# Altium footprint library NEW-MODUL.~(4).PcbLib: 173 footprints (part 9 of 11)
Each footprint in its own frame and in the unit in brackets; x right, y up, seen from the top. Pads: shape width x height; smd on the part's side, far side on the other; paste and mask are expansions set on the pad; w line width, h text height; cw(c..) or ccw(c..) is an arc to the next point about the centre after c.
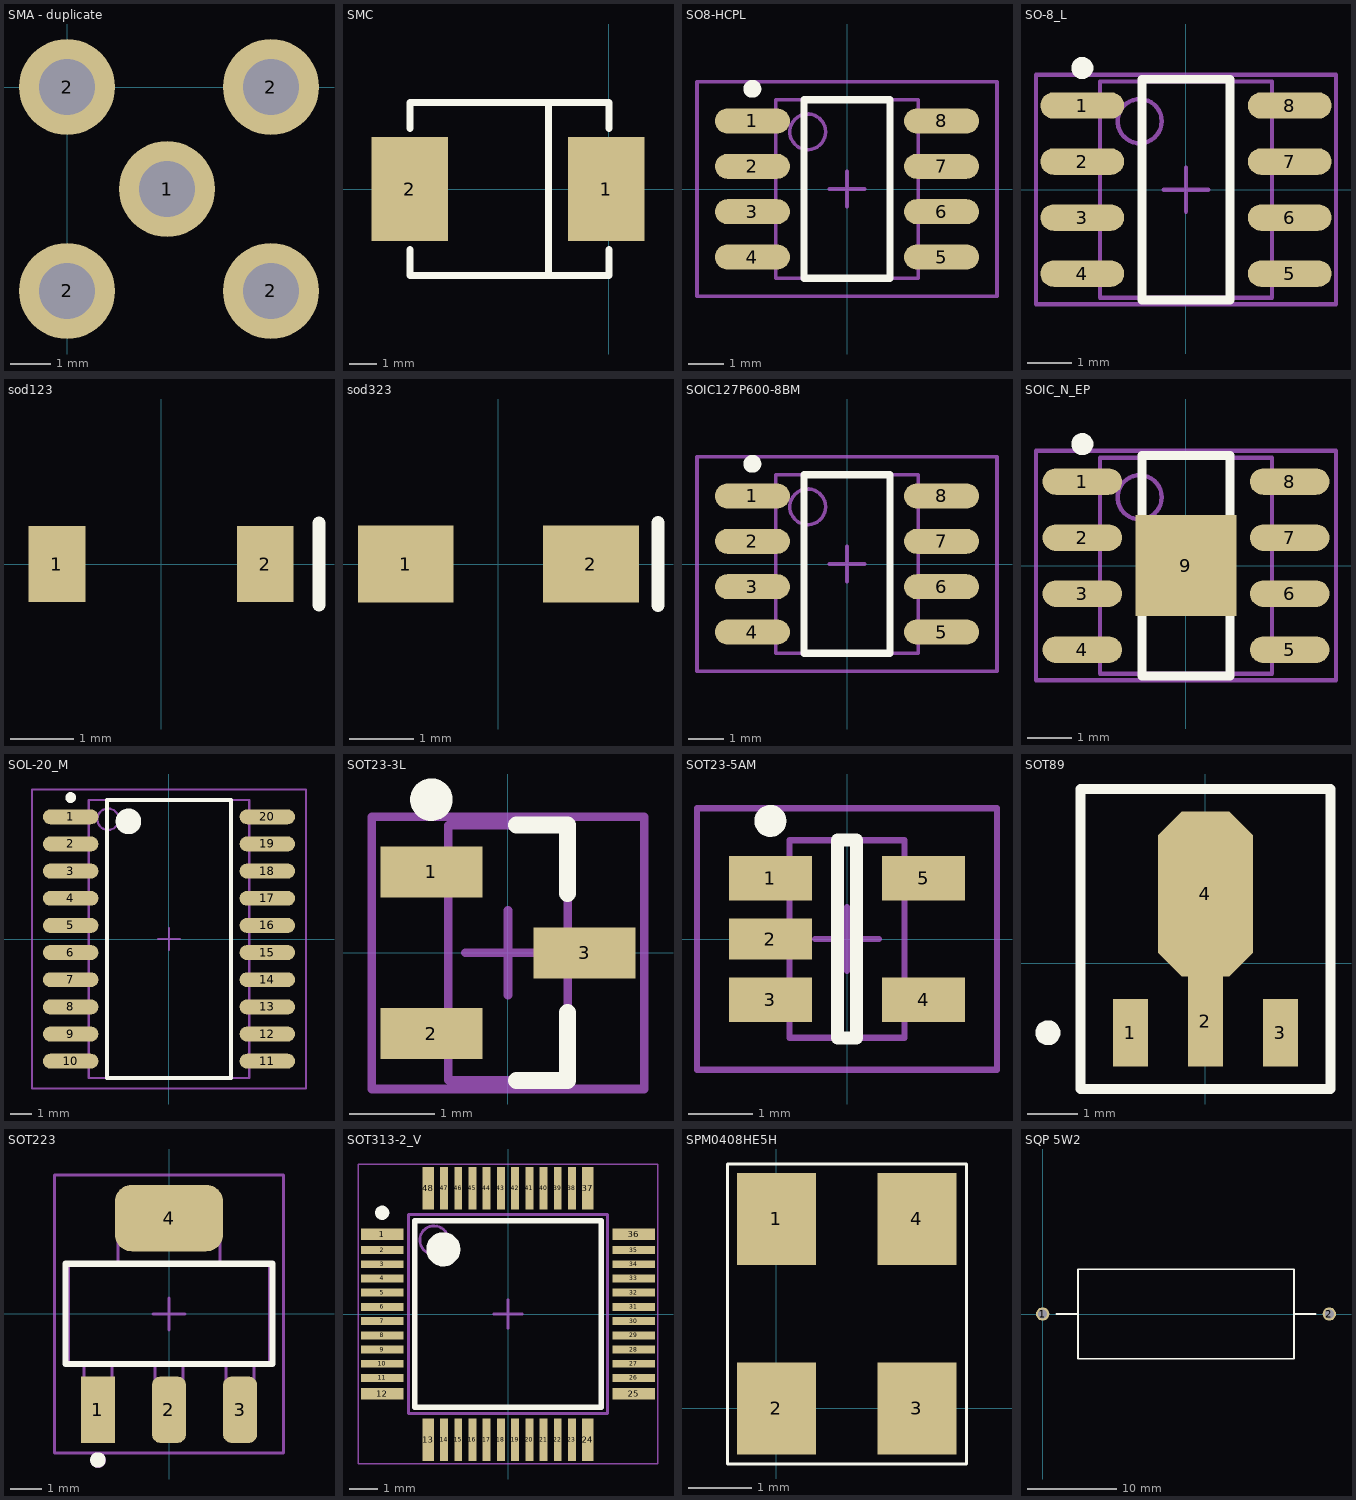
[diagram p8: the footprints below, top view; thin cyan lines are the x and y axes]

## SMA - duplicate [mm]
pads (5):
  round 2.4 hole 1.4: 1(2.5,-2.55) 2(0,-5.1) 2(0,0) 2(5.1,-5.1) 2(5.1,0)
3D body "11945.stp": height 10.43, standoff -3.41, extent -0.7,-13.7 5.64,0.5

## SMC [mm]
pads (2):
  rect 2.8x3.8 smd: 1(-0.102,0) 2(-7.302,0)
Top Overlay:
  lines w0.254: -7.302,-2.222 -7.302,-3.175 0,-3.175 0,-2.222 ; -7.302,2.222 -7.302,3.175 0,3.175 0,2.222 ; -2.222,-3.175 -2.222,3.175
3D body "User Library-Diode Molded Body.step": height 2.18, standoff 0.02, extent -7.633,-3 0.267,3

## SO8-HCPL [mm] "SOIC, 8-Leads, Body 4.9x3.9mm, Pitch 1.27mm, IPC Low Density"
height 2.59
pads (8):
  oval 2.1x0.7 smd: 1(-2.65,1.905) 2(-2.65,0.635) 3(-2.65,-0.635) 4(-2.65,-1.905) 5(2.65,-1.905) 6(2.65,-0.635) 7(2.65,0.635) 8(2.65,1.905)
Top Overlay:
  circle w0.25: c-2.65,2.805 r0.125
  lines w0.2: -1.2,-2.5 1.2,-2.5 1.2,2.5 -1.2,2.5 -1.2,-2.5
Mechanical 13:
  circle w0.1: c-1.1,1.6 r0.5
  lines w0.1: -2,-2.5 2,-2.5 2,2.5 -2,2.5 -2,-2.5
Mechanical 15:
  lines w0.1: -0.5,0 0.5,0 ; 0,-0.5 0,0.5 ; -4.2,-3 4.2,-3 4.2,3 -4.2,3 -4.2,-3
3D body "SW3dPS-SO8-HCPL.STEP": height 3.33, standoff -0.4, extent -2.997,-2.5 3.008,2.5

## SO-8_L [mm] "8-Pin Small Outline Integrated Circuit 1.27 mm Pitch, IPC High Density"
height 1.75
pads (8):
  oval 1.9x0.6 smd: 1(-2.35,1.905) 2(-2.35,0.635) 3(-2.35,-0.635) 4(-2.35,-1.905) 5(2.35,-1.905) 6(2.35,-0.635) 7(2.35,0.635) 8(2.35,1.905)
Top Overlay:
  circle w0.25: c-2.35,2.755 r0.125
  lines w0.2: -1,-2.5 1,-2.5 1,2.5 -1,2.5 -1,-2.5
Mechanical 13:
  circle w0.1: c-1.05,1.55 r0.5
  lines w0.1: -1.95,-2.45 1.95,-2.45 1.95,2.45 -1.95,2.45 -1.95,-2.45
Mechanical 15:
  lines w0.1: -0.5,0 0.5,0 ; 0,-0.5 0,0.5 ; -3.4,-2.6 3.4,-2.6 3.4,2.6 -3.4,2.6 -3.4,-2.6
3D body "User Library-SOIC-8-1.step": height 1.75, standoff 0, extent -3,-2.45 3,2.45

## sod123 [mm]
pads (2):
  rect 0.9x1.2 smd: 1(-1.65,0) 2(1.65,0)
Top Overlay:
  lines w0.2: 2.5,-0.65 2.5,0.65
3D body "User Library-SOD-123_DiodesInc.step": height 1.46, standoff 0.01, extent -1.925,-0.838 1.925,0.862

## sod323 [mm]
pads (2):
  rect 1.5x1.2 smd: 1(-1.45,0) 2(1.45,0)
Top Overlay:
  lines w0.2: 2.5,-0.65 2.5,0.65
3D body "SW3dPS-SOD-323F.STEP": height 0.79, standoff -0.08, extent -1.35,-0.675 1.35,0.675

## SOIC127P600-8BM [mm] "SOIC, 8-Leads, Body 4.9x3.9mm, Pitch 1.27mm, IPC Low Density"
height 2.59
pads (8):
  oval 2.1x0.7 smd: 1(-2.65,1.905) 2(-2.65,0.635) 3(-2.65,-0.635) 4(-2.65,-1.905) 5(2.65,-1.905) 6(2.65,-0.635) 7(2.65,0.635) 8(2.65,1.905)
Top Overlay:
  circle w0.25: c-2.65,2.805 r0.125
  lines w0.2: -1.2,-2.5 -1.2,2.5 1.2,2.5 1.2,-2.5 -1.2,-2.5
Mechanical 13:
  circle w0.1: c-1.1,1.6 r0.5
  lines w0.1: -2,-2.5 -2,2.5 2,2.5 2,-2.5 -2,-2.5
Mechanical 15:
  lines w0.1: -0.5,0 0.5,0 ; 0,-0.5 0,0.5 ; -4.2,-3 -4.2,3 4.2,3 4.2,-3 -4.2,-3
3D body "User Library-SOIC-8-1.step": height 1.75, standoff 0, extent -3.025,-2.45 2.975,2.45

## SOIC_N_EP [mm] "8-Pin Small Outline Integrated Circuit 1.27 mm Pitch, IPC High Density"
height 1.75
pads (9):
  oval 1.8x0.6 smd: 1(-2.35,1.905) 2(-2.35,0.635) 3(-2.35,-0.635) 4(-2.35,-1.905) 5(2.35,-1.905) 6(2.35,-0.635) 7(2.35,0.635) 8(2.35,1.905)
  rect 2.29x2.29 smd: 9(0,0)
Top Overlay:
  circle w0.25: c-2.35,2.755 r0.125
  lines w0.2: -1,-2.5 -1,2.5 1,2.5 1,-2.5 -1,-2.5
Mechanical 13:
  circle w0.1: c-1.05,1.55 r0.5
  lines w0.1: -1.95,-2.45 -1.95,2.45 1.95,2.45 1.95,-2.45 -1.95,-2.45
Mechanical 15:
  lines w0.1: -0.5,0 0.5,0 ; 0,-0.5 0,0.5 ; -3.4,-2.6 -3.4,2.6 3.4,2.6 3.4,-2.6 -3.4,-2.6
3D body "User Library-SOIC-8-1.step": height 1.75, standoff 0, extent -3,-2.45 3,2.45

## SOL-20_M [mm] "20-Pin Small Outline Integrated Circuit 1.27 mm Pitch, IPC Low Density"
height 2.65
pads (20):
  oval 2.6x0.7 smd: 1(-4.6,5.715) 2(-4.6,4.445) 3(-4.6,3.175) 4(-4.6,1.905) 5(-4.6,0.635) 6(-4.6,-0.635) 7(-4.6,-1.905) 8(-4.6,-3.175) 9(-4.6,-4.445) 10(-4.6,-5.715) 11(4.6,-5.715) 12(4.6,-4.445) 13(4.6,-3.175) 14(4.6,-1.905) 15(4.6,-0.635) 16(4.6,0.635) 17(4.6,1.905) 18(4.6,3.175) 19(4.6,4.445) 20(4.6,5.715)
Top Overlay:
  circle w0.25: c-4.6,6.615 r0.125
  circle w0.6: c-1.9,5.5 r0.3
  lines w0.2: -2.9,-6.5 -2.9,6.5 2.9,6.5 2.9,-6.5 -2.9,-6.5
Mechanical 13:
  circle w0.1: c-2.85,5.6 r0.5
  lines w0.1: -3.75,-6.5 -3.75,6.5 3.75,6.5 3.75,-6.5 -3.75,-6.5
Mechanical 15:
  lines w0.1: -0.5,0 0.5,0 ; 0,-0.5 0,0.5 ; -6.4,-7 -6.4,7 6.4,7 6.4,-7 -6.4,-7
3D body "CircuitWorks-SOL-20.step": height 1.75, standoff 0, extent -4.55,-6.5 4.75,6.45

## SOT23-3L [mm] "SOT23, 3-Leads, Body 2.9x1.3mm, Pitch 0.95mm, Lead Span 2.5mm, IPC High Density"
height 1.1
pads (3):
  rect 1.2x0.6 smd: 1(-0.9,0.95) 2(-0.9,-0.95) 3(0.9,0)
Top Overlay:
  circle w0.25: c-0.9,1.8 r0.125
  lines w0.2: 0.1,-1.5 0.7,-1.5 0.7,-0.7 ; 0.1,1.5 0.7,1.5 0.7,0.7
Mechanical 13:
  lines w0.1: -0.7,-1.5 0.7,-1.5 0.7,1.5 -0.7,1.5 -0.7,-1.5
Mechanical 15:
  lines w0.1: -0.5,0 0.5,0 ; 0,-0.5 0,0.5 ; -1.6,-1.6 1.6,-1.6 1.6,1.6 -1.6,1.6 -1.6,-1.6
3D body "User Library-BAT54.step": height 1, standoff 0, extent -1.297,-1.46 1.043,1.46

## SOT23-5AM [mm] "SOT23, 5-Leads, Body 2.9x1.7mm, Pitch 0.95mm, Lead Span 2.8mm, IPC Low Density"
height 1.45
pads (5):
  rect 1.3x0.7 smd: 1(-1.2,0.95) 3(-1.2,-0.95) 4(1.2,-0.95) 5(1.2,0.95)
  rect 1.3x0.65 smd: 2(-1.2,0)
Top Overlay:
  circle w0.25: c-1.2,1.85 r0.125
  lines w0.2: -0.15,-1.55 0.15,-1.55 0.15,1.55 -0.15,1.55 -0.15,-1.55
Mechanical 13:
  lines w0.1: -0.9,-1.55 -0.9,1.55 0.9,1.55 0.9,-1.55 -0.9,-1.55
Mechanical 15:
  lines w0.1: -0.5,0 0.5,0 ; 0,-0.5 0,0.5 ; -2.35,-2.05 -2.35,2.05 2.35,2.05 2.35,-2.05 -2.35,-2.05
3D body "User Library-SOT23-5-1.step": height 1.3, standoff 0, extent -1.5,-1.5 1.5,1.5

## SOT89 [mm] "SOT-89; Body 4.6 x 4.25 mm, inc. leads (LxW max)"
height 1.6
pads (4):
  rect 0.7x1.35 smd: 1(-1.5,-1.388) 3(1.5,-1.388)
  rect 0.7x1.8 smd: 2(0,-1.162)
  oct 1.9x3.3 smd: 4(0,1.388)
Top Overlay:
  circle w0.25: c-3.15,-1.388 r0.125
  lines w0.2: -2.5,-2.512 -2.5,3.487 2.5,3.487 2.5,-2.512 -2.5,-2.512
3D body "User Library-SOT-89-1.step": height 1.51, standoff 0, extent -2.25,-1.7 2.25,2.6

## SOT223 [mm] "SOT-223/SC-73; 4 Leads; Body 6.7 x 7.3 mm, inc. leads (LxW max)"
height 1.8
pads (4):
  rect 1.1x2.15 smd mask+0.1: 1(-2.3,-3.1)
  rrect50% 1.1x2.15 smd mask+0.1: 2(0,-3.1) 3(2.3,-3.1)
  rrect50% 3.5x2.15 smd mask+0.1: 4(0,3.1)
Top Overlay:
  circle w0.25: c-2.3,-4.725 r0.125
  lines w0.2: -3.35,-1.625 -3.35,1.625 3.35,1.625 3.35,-1.625 -3.35,-1.625
Mechanical 1:
  circle w0.25: c-2.295,-4.73 r0.125
  lines w0.1: -2.75,-1.63 -2.75,-3.48 -1.85,-3.48 -1.85,-1.62 ; -1.65,1.63 -1.65,3.48 1.65,3.48 1.65,1.63 ; -0.45,-1.62 -0.45,-3.47 0.45,-3.47 0.45,-1.61 ; 1.85,-1.63 1.85,-3.48 2.75,-3.48 2.75,-1.62 ; -3.25,-1.62 -3.25,1.63 3.25,1.63 3.25,-1.62 -3.25,-1.62
Mechanical 15:
  lines w0.1: -0.52,0 0,0 ; 0,-0.52 0,0 ; 0,0.52 0,0 ; 0.52,0 0,0 ; -3.7,-4.5 -3.7,0.1 -3.7,4.5 3.7,4.5 3.7,-4.5 -3.7,-4.5
3D body "LM1117.STEP": height 1.65, standoff -0.03, extent -3.25,-3.48 3.25,3.48

## SOT313-2_V [mm] "Thin QFP, 48-Leads, Body 7x7mm, Pitch 0.5mm, NXP Recommended"
height 1.6
pads (48):
  rect 1.5x0.4 smd: 1(-4.425,2.81) 12(-4.425,-2.81) 25(4.425,-2.81) 36(4.425,2.81)
  rect 1.5x0.28 smd: 2(-4.425,2.25) 3(-4.425,1.75) 4(-4.425,1.25) 5(-4.425,0.75) 6(-4.425,0.25) 7(-4.425,-0.25) 8(-4.425,-0.75) 9(-4.425,-1.25) 10(-4.425,-1.75) 11(-4.425,-2.25) 26(4.425,-2.25) 27(4.425,-1.75) 28(4.425,-1.25) 29(4.425,-0.75) 30(4.425,-0.25) 31(4.425,0.25) 32(4.425,0.75) 33(4.425,1.25) 34(4.425,1.75) 35(4.425,2.25)
  rect 0.4x1.5 smd: 13(-2.81,-4.425) 24(2.81,-4.425) 37(2.81,4.425) 48(-2.81,4.425)
  rect 0.28x1.5 smd: 14(-2.25,-4.425) 15(-1.75,-4.425) 16(-1.25,-4.425) 17(-0.75,-4.425) 18(-0.25,-4.425) 19(0.25,-4.425) 20(0.75,-4.425) 21(1.25,-4.425) 22(1.75,-4.425) 23(2.25,-4.425) 38(2.25,4.425) 39(1.75,4.425) 40(1.25,4.425) 41(0.75,4.425) 42(0.25,4.425) 43(-0.25,4.425) 44(-0.75,4.425) 45(-1.25,4.425) 46(-1.75,4.425) 47(-2.25,4.425)
Top Overlay:
  circle w0.25: c-4.425,3.56 r0.125
  circle w0.6: c-2.275,2.275 r0.3
  lines w0.2: -3.275,-3.275 -3.275,3.275 3.275,3.275 3.275,-3.275 -3.275,-3.275
Mechanical 13:
  circle w0.1: c-2.6,2.6 r0.5
  lines w0.1: -3.5,-3.5 -3.5,3.5 3.5,3.5 3.5,-3.5 -3.5,-3.5
Mechanical 15:
  lines w0.05: -5.275,-5.275 -5.275,5.275 5.275,5.275 5.275,-5.275 -5.275,-5.275
  lines w0.1: -0.5,0 0.5,0 ; 0,-0.5 0,0.5
3D body "User Library-LQFP48_Grid_0_5.STEP": height 1.6, standoff 0, extent -4.5,-4.5 4.5,4.5

## SPM0408HE5H [mm]
pads (4):
  rect 1.24x1.45 smd: 1(0,2.98) 2(0,0) 3(2.21,0) 4(2.21,2.98)
Top Overlay:
  lines w0.05: -0.77,-0.875 -0.77,3.845 2.99,3.845 2.99,-0.875 -0.77,-0.875

## SQP 5W2 [mm]
pads (2):
  round 1.5 hole 1: 1(0,0) 2(32,0)
Top Overlay:
  lines w0.2: 1.5,0 3.925,0 ; 28,-5 3.925,-5 3.925,0 ; 28,5 3.925,5 3.925,0 ; 28.075,-5 28.075,5 ; 28.075,0 30.5,0
3D body "User Library-SQP-5W-2.STEP": height 9, standoff -2.5, extent -0.35,-5 32.35,5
